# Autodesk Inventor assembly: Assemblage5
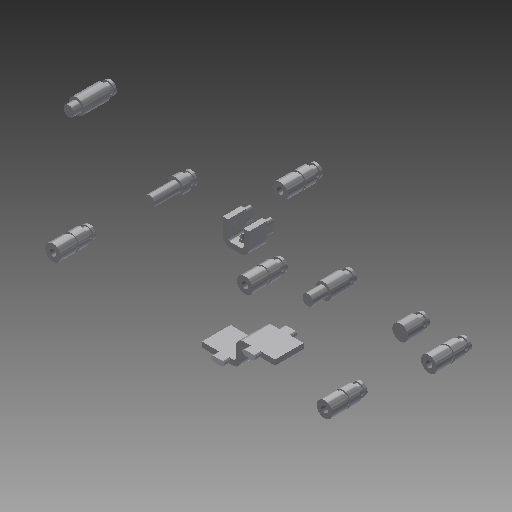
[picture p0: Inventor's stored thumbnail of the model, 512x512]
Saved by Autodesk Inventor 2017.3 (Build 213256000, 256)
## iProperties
Created: 2007-12
Part Number: Assemblage5
Material: Générique
Document SubType Name: Assembly
Designer: ficho
Author: ficho
Sending System: SolidWorks 2009
Last Author: christophe
Last Saved: 2011-02-10
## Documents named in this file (8)
- G:\travail\année 2019-2020\réforme\toussaint\Serrure biométrique SET\Documentations_pedagogique\Modelisation_Solidworks\Assemblage5.iam
- G:\travail\année 2019-2020\réforme\toussaint\Serrure biométrique SET\Documentations_pedagogique\Modelisation_Solidworks\Pièce20.ipt
- G:\travail\année 2019-2020\réforme\toussaint\Serrure biométrique SET\Documentations_pedagogique\Modelisation_Solidworks\Pièce21.ipt
- G:\travail\année 2019-2020\réforme\toussaint\Serrure biométrique SET\Documentations_pedagogique\Modelisation_Solidworks\Pièce23.ipt
- G:\travail\année 2019-2020\réforme\toussaint\Serrure biométrique SET\Documentations_pedagogique\Modelisation_Solidworks\Pièce22.ipt
- G:\travail\année 2019-2020\réforme\toussaint\Serrure biométrique SET\Documentations_pedagogique\Modelisation_Solidworks\Pièce24.ipt
- G:\travail\année 2019-2020\réforme\toussaint\Serrure biométrique SET\Documentations_pedagogique\Modelisation_Solidworks\Pièce25.ipt
- G:\travail\année 2019-2020\réforme\toussaint\Serrure biométrique SET\Documentations_pedagogique\Modelisation_Solidworks\Pièce38.ipt
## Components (11 placed, 7 different names)
1. Pièce20:1
2. Pièce20:2
3. Pièce20:3
4. Pièce20:4
5. Pièce20:5
6. Pièce21:1
7. Pièce23:1
8. Pièce22:2
9. Pièce24:1
10. Pièce25:1
11. Pièce38:1
